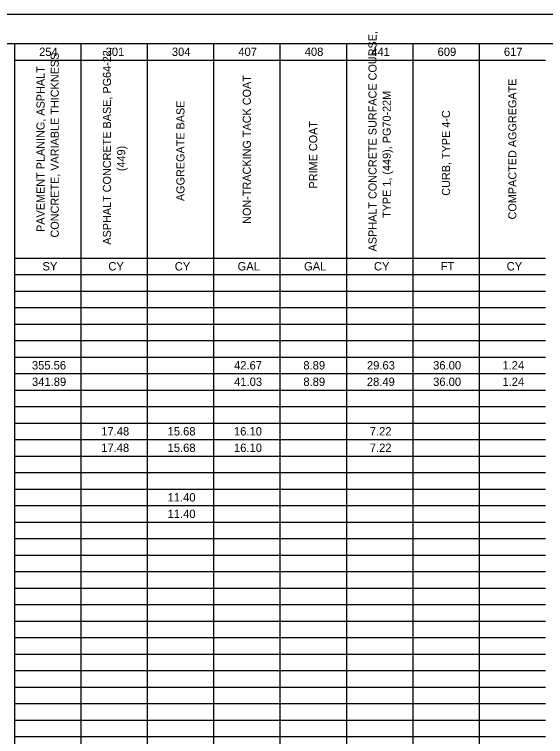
# Model space of a CAD drawing. Extents: x 0 to 34, y 0 to 22.
# Drawn here: x 16.02 to 25.15, y 9.58 to 22 of the extents above; entities that cross this region are included whole.
import ezdxf

# ---------------------------------------------------------------- set-up
doc = ezdxf.new("R2010")
doc.units = 0
for name, color, linetype in [('SH_Border', 7, 'Continuous'), ('SH_Cut_Line', 7, 'Continuous'), ('SH_Text', 7, 'Continuous')]:
    doc.layers.add(name, color=color, linetype=linetype)

msp = doc.modelspace()

# ---------------------------------------------------------------- linework, layer by layer
at = {"layer": 'SH_Border'}
msp.add_lwpolyline([(1.5, 21.5), (33.5, 21.5), (33.5, 0.5), (1.5, 0.5)], close=True, dxfattribs=at)
at = {"layer": 'SH_Cut_Line'}
msp.add_lwpolyline([(0, 0), (34, 0), (34, 22), (0, 22)], close=True, dxfattribs=at)
at = {"layer": 'SH_Text'}
for p, q in [((16.022, 21.5), (24.011, 21.5)), ((16.022, 21.5), (16.022, 21.216)), ((17.163, 21.5), (17.163, 21.216)), ((18.305, 21.5), (18.305, 21.216)), ((19.446, 21.5), (19.446, 21.216)), ((20.587, 21.5), (20.587, 21.216)), ((21.728, 21.5), (21.728, 21.216)), ((22.87, 21.5), (22.87, 21.216)), ((24.011, 21.5), (25.152, 21.5)), ((24.011, 21.5), (24.011, 21.216)), ((16.022, 21.216), (24.011, 21.216)), ((16.022, 21.216), (16.022, 20.932)), ((17.163, 21.216), (17.163, 20.932)), ((18.305, 21.216), (18.305, 20.932)), ((19.446, 21.216), (19.446, 20.932)), ((20.587, 21.216), (20.587, 20.932)), ((21.728, 21.216), (21.728, 20.932)), ((22.87, 21.216), (22.87, 20.932)), ((24.011, 21.216), (25.152, 21.216)), ((24.011, 21.216), (24.011, 20.932)), ((16.022, 20.932), (16.022, 20.649)), ((17.163, 20.932), (17.163, 20.649)), ((18.305, 20.932), (18.305, 20.649)), ((19.446, 20.932), (19.446, 20.649)), ((20.587, 20.932), (20.587, 20.649)), ((21.728, 20.932), (21.728, 20.649)), ((22.87, 20.932), (22.87, 20.649)), ((24.011, 20.932), (24.011, 20.649)), ((16.022, 20.649), (16.022, 20.081)), ((17.163, 20.649), (17.163, 20.081)), ((18.305, 20.649), (18.305, 20.081)), ((19.446, 20.649), (19.446, 20.081)), ((20.587, 20.649), (20.587, 20.081)), ((21.728, 20.649), (21.728, 20.081)), ((22.87, 20.649), (22.87, 20.081)), ((24.011, 20.649), (24.011, 20.081)), ((16.022, 20.081), (16.022, 19.797)), ((17.163, 20.081), (17.163, 19.797)), ((18.305, 20.081), (18.305, 19.797)), ((19.446, 20.081), (19.446, 19.797)), ((20.587, 20.081), (20.587, 19.797)), ((21.728, 20.081), (21.728, 19.797)), ((22.87, 20.081), (22.87, 19.797)), ((24.011, 20.081), (24.011, 19.797)), ((16.022, 19.797), (16.022, 19.514)), ((17.163, 19.797), (17.163, 19.514)), ((18.305, 19.797), (18.305, 19.514)), ((19.446, 19.797), (19.446, 19.514)), ((20.587, 19.797), (20.587, 19.514)), ((21.728, 19.797), (21.728, 19.514)), ((22.87, 19.797), (22.87, 19.514)), ((24.011, 19.797), (24.011, 19.514)), ((16.022, 19.514), (16.022, 19.23)), ((17.163, 19.514), (17.163, 19.23)), ((18.305, 19.514), (18.305, 19.23)), ((19.446, 19.514), (19.446, 19.23)), ((20.587, 19.514), (20.587, 19.23)), ((21.728, 19.514), (21.728, 19.23)), ((22.87, 19.514), (22.87, 19.23)), ((24.011, 19.514), (24.011, 19.23)), ((16.022, 19.23), (16.022, 18.946)), ((17.163, 19.23), (17.163, 18.946)), ((18.305, 19.23), (18.305, 18.946)), ((19.446, 19.23), (19.446, 18.946)), ((20.587, 19.23), (20.587, 18.946)), ((21.728, 19.23), (21.728, 18.946)), ((22.87, 19.23), (22.87, 18.946)), ((24.011, 19.23), (24.011, 18.946)), ((16.022, 18.946), (16.022, 18.662)), ((17.163, 18.946), (17.163, 18.662)), ((18.305, 18.946), (18.305, 18.662)), ((19.446, 18.946), (19.446, 18.662)), ((20.587, 18.946), (20.587, 18.662)), ((21.728, 18.946), (21.728, 18.662)), ((22.87, 18.946), (22.87, 18.662)), ((24.011, 18.946), (24.011, 18.662)), ((16.022, 18.662), (16.022, 18.378)), ((17.163, 18.662), (17.163, 18.378)), ((18.305, 18.662), (18.305, 18.378)), ((19.446, 18.662), (19.446, 18.378)), ((20.587, 18.662), (20.587, 18.378)), ((21.728, 18.662), (21.728, 18.378)), ((22.87, 18.662), (22.87, 18.378)), ((24.011, 18.662), (24.011, 18.378)), ((16.022, 18.378), (16.022, 18.095)), ((17.163, 18.378), (17.163, 18.095)), ((18.305, 18.378), (18.305, 18.095)), ((19.446, 18.378), (19.446, 18.095)), ((20.587, 18.378), (20.587, 18.095)), ((21.728, 18.378), (21.728, 18.095)), ((22.87, 18.378), (22.87, 18.095)), ((24.011, 18.378), (24.011, 18.095)), ((16.022, 18.095), (16.022, 17.811)), ((17.163, 18.095), (17.163, 17.811)), ((18.305, 18.095), (18.305, 17.811)), ((19.446, 18.095), (19.446, 17.811)), ((20.587, 18.095), (20.587, 17.811)), ((21.728, 18.095), (21.728, 17.811)), ((22.87, 18.095), (22.87, 17.811)), ((24.011, 18.095), (24.011, 17.811)), ((16.022, 17.811), (24.011, 17.811)), ((16.022, 17.811), (16.022, 17.527)), ((17.163, 17.811), (17.163, 17.527)), ((18.305, 17.811), (18.305, 17.527)), ((19.446, 17.811), (19.446, 17.527)), ((20.587, 17.811), (20.587, 17.527)), ((21.728, 17.811), (21.728, 17.527)), ((22.87, 17.811), (22.87, 17.527)), ((24.011, 17.811), (25.152, 17.811)), ((24.011, 17.811), (24.011, 17.527)), ((16.022, 17.527), (24.011, 17.527)), ((16.022, 17.527), (16.022, 17.243)), ((17.163, 17.527), (17.163, 17.243)), ((18.305, 17.527), (18.305, 17.243)), ((19.446, 17.527), (19.446, 17.243)), ((20.587, 17.527), (20.587, 17.243)), ((21.728, 17.527), (21.728, 17.243)), ((22.87, 17.527), (22.87, 17.243)), ((24.011, 17.527), (25.152, 17.527)), ((24.011, 17.527), (24.011, 17.243)), ((16.022, 17.243), (24.011, 17.243)), ((16.022, 17.243), (16.022, 16.959)), ((17.163, 17.243), (17.163, 16.959)), ((18.305, 17.243), (18.305, 16.959)), ((19.446, 17.243), (19.446, 16.959)), ((20.587, 17.243), (20.587, 16.959)), ((21.728, 17.243), (21.728, 16.959)), ((22.87, 17.243), (22.87, 16.959)), ((24.011, 17.243), (25.152, 17.243)), ((24.011, 17.243), (24.011, 16.959)), ((16.022, 16.959), (24.011, 16.959)), ((16.022, 16.959), (16.022, 16.676)), ((17.163, 16.959), (17.163, 16.676)), ((18.305, 16.959), (18.305, 16.676)), ((19.446, 16.959), (19.446, 16.676)), ((20.587, 16.959), (20.587, 16.676)), ((21.728, 16.959), (21.728, 16.676)), ((22.87, 16.959), (22.87, 16.676)), ((24.011, 16.959), (25.152, 16.959)), ((24.011, 16.959), (24.011, 16.676)), ((16.022, 16.676), (24.011, 16.676)), ((16.022, 16.676), (16.022, 16.108)), ((17.163, 16.676), (17.163, 16.108)), ((18.305, 16.676), (18.305, 16.108)), ((19.446, 16.676), (19.446, 16.108)), ((20.587, 16.676), (20.587, 16.108)), ((21.728, 16.676), (21.728, 16.108)), ((22.87, 16.676), (22.87, 16.108)), ((24.011, 16.676), (25.152, 16.676)), ((24.011, 16.676), (24.011, 16.108)), ((16.022, 16.392), (24.011, 16.392)), ((24.011, 16.392), (25.152, 16.392)), ((16.022, 16.108), (24.011, 16.108)), ((16.022, 16.108), (16.022, 15.824)), ((17.163, 16.108), (17.163, 15.824)), ((18.305, 16.108), (18.305, 15.824)), ((19.446, 16.108), (19.446, 15.824)), ((20.587, 16.108), (20.587, 15.824)), ((21.728, 16.108), (21.728, 15.824)), ((22.87, 16.108), (22.87, 15.824)), ((24.011, 16.108), (25.152, 16.108)), ((24.011, 16.108), (24.011, 15.824)), ((16.022, 15.824), (24.011, 15.824)), ((16.022, 15.824), (16.022, 15.541)), ((17.163, 15.824), (17.163, 15.541)), ((18.305, 15.824), (18.305, 15.541)), ((19.446, 15.824), (19.446, 15.541)), ((20.587, 15.824), (20.587, 15.541)), ((21.728, 15.824), (21.728, 15.541)), ((22.87, 15.824), (22.87, 15.541)), ((24.011, 15.824), (25.152, 15.824)), ((24.011, 15.824), (24.011, 15.541)), ((16.022, 15.541), (24.011, 15.541)), ((16.022, 15.541), (16.022, 15.257)), ((17.163, 15.541), (17.163, 15.257)), ((18.305, 15.541), (18.305, 15.257)), ((19.446, 15.541), (19.446, 15.257)), ((20.587, 15.541), (20.587, 15.257)), ((21.728, 15.541), (21.728, 15.257)), ((22.87, 15.541), (22.87, 15.257)), ((24.011, 15.541), (25.152, 15.541)), ((24.011, 15.541), (24.011, 15.257)), ((16.022, 15.257), (24.011, 15.257)), ((16.022, 15.257), (16.022, 14.689)), ((17.163, 15.257), (17.163, 14.689)), ((18.305, 15.257), (18.305, 14.689)), ((19.446, 15.257), (19.446, 14.689)), ((20.587, 15.257), (20.587, 14.689)), ((21.728, 15.257), (21.728, 14.689)), ((22.87, 15.257), (22.87, 14.689)), ((24.011, 15.257), (25.152, 15.257)), ((24.011, 15.257), (24.011, 14.689)), ((16.022, 14.973), (24.011, 14.973)), ((24.011, 14.973), (25.152, 14.973)), ((16.022, 14.689), (24.011, 14.689)), ((16.022, 14.689), (16.022, 14.405)), ((17.163, 14.689), (17.163, 14.405)), ((18.305, 14.689), (18.305, 14.405)), ((19.446, 14.689), (19.446, 14.405)), ((20.587, 14.689), (20.587, 14.405)), ((21.728, 14.689), (21.728, 14.405)), ((22.87, 14.689), (22.87, 14.405)), ((24.011, 14.689), (25.152, 14.689)), ((24.011, 14.689), (24.011, 14.405)), ((16.022, 14.405), (24.011, 14.405)), ((16.022, 14.405), (16.022, 14.122)), ((17.163, 14.405), (17.163, 14.122)), ((18.305, 14.405), (18.305, 14.122)), ((19.446, 14.405), (19.446, 14.122)), ((20.587, 14.405), (20.587, 14.122)), ((21.728, 14.405), (21.728, 14.122)), ((22.87, 14.405), (22.87, 14.122)), ((24.011, 14.405), (25.152, 14.405)), ((24.011, 14.405), (24.011, 14.122)), ((16.022, 14.122), (24.011, 14.122)), ((16.022, 14.122), (16.022, 13.838)), ((17.163, 14.122), (17.163, 13.838)), ((18.305, 14.122), (18.305, 13.838)), ((19.446, 14.122), (19.446, 13.838)), ((20.587, 14.122), (20.587, 13.838)), ((21.728, 14.122), (21.728, 13.838)), ((22.87, 14.122), (22.87, 13.838)), ((24.011, 14.122), (25.152, 14.122)), ((24.011, 14.122), (24.011, 13.838)), ((16.022, 13.838), (24.011, 13.838)), ((16.022, 13.838), (16.022, 12.986)), ((17.163, 13.838), (17.163, 12.986)), ((18.305, 13.838), (18.305, 12.986)), ((19.446, 13.838), (19.446, 12.986)), ((20.587, 13.838), (20.587, 12.986)), ((21.728, 13.838), (21.728, 12.986)), ((22.87, 13.838), (22.87, 12.986)), ((24.011, 13.838), (25.152, 13.838)), ((24.011, 13.838), (24.011, 12.986)), ((16.022, 13.554), (24.011, 13.554)), ((24.011, 13.554), (25.152, 13.554)), ((16.022, 13.27), (24.011, 13.27)), ((24.011, 13.27), (25.152, 13.27)), ((16.022, 12.986), (24.011, 12.986)), ((16.022, 12.986), (16.022, 12.703)), ((17.163, 12.986), (17.163, 12.703)), ((18.305, 12.986), (18.305, 12.703)), ((19.446, 12.986), (19.446, 12.703)), ((20.587, 12.986), (20.587, 12.703)), ((21.728, 12.986), (21.728, 12.703)), ((22.87, 12.986), (22.87, 12.703)), ((24.011, 12.986), (25.152, 12.986)), ((24.011, 12.986), (24.011, 12.703)), ((16.022, 12.703), (24.011, 12.703)), ((16.022, 12.703), (16.022, 11.568)), ((17.163, 12.703), (17.163, 11.568)), ((18.305, 12.703), (18.305, 11.568)), ((19.446, 12.703), (19.446, 11.568)), ((20.587, 12.703), (20.587, 11.568)), ((21.728, 12.703), (21.728, 11.568)), ((22.87, 12.703), (22.87, 11.568)), ((24.011, 12.703), (25.152, 12.703)), ((24.011, 12.703), (24.011, 11.568)), ((16.022, 12.419), (24.011, 12.419)), ((24.011, 12.419), (25.152, 12.419)), ((16.022, 12.135), (24.011, 12.135)), ((24.011, 12.135), (25.152, 12.135)), ((16.022, 11.851), (24.011, 11.851)), ((24.011, 11.851), (25.152, 11.851)), ((16.022, 11.568), (24.011, 11.568)), ((16.022, 11.568), (16.022, 11.284)), ((17.163, 11.568), (17.163, 11.284)), ((18.305, 11.568), (18.305, 11.284)), ((19.446, 11.568), (19.446, 11.284)), ((20.587, 11.568), (20.587, 11.284)), ((21.728, 11.568), (21.728, 11.284)), ((22.87, 11.568), (22.87, 11.284)), ((24.011, 11.568), (25.152, 11.568)), ((24.011, 11.568), (24.011, 11.284)), ((16.022, 11.284), (24.011, 11.284)), ((16.022, 11.284), (16.022, 10.149)), ((17.163, 11.284), (17.163, 10.149)), ((18.305, 11.284), (18.305, 10.149)), ((19.446, 11.284), (19.446, 10.149)), ((20.587, 11.284), (20.587, 10.149)), ((21.728, 11.284), (21.728, 10.149)), ((22.87, 11.284), (22.87, 10.149)), ((24.011, 11.284), (25.152, 11.284)), ((24.011, 11.284), (24.011, 10.149)), ((16.022, 11), (24.011, 11)), ((24.011, 11), (25.152, 11)), ((16.022, 10.716), (24.011, 10.716)), ((24.011, 10.716), (25.152, 10.716)), ((16.022, 10.432), (24.011, 10.432)), ((24.011, 10.432), (25.152, 10.432)), ((16.022, 10.149), (24.011, 10.149)), ((16.022, 10.149), (16.022, 9.581)), ((17.163, 10.149), (17.163, 9.581)), ((18.305, 10.149), (18.305, 9.581)), ((19.446, 10.149), (19.446, 9.581)), ((20.587, 10.149), (20.587, 9.581)), ((21.728, 10.149), (21.728, 9.581)), ((22.87, 10.149), (22.87, 9.581)), ((24.011, 10.149), (25.152, 10.149)), ((24.011, 10.149), (24.011, 9.581)), ((16.022, 9.865), (24.011, 9.865)), ((24.011, 9.865), (25.152, 9.865)), ((16.022, 9.581), (24.011, 9.581)), ((16.022, 9.581), (16.022, 9.297)), ((17.163, 9.581), (17.163, 9.297)), ((18.305, 9.581), (18.305, 9.297)), ((19.446, 9.581), (19.446, 9.297)), ((20.587, 9.581), (20.587, 9.297)), ((21.728, 9.581), (21.728, 9.297)), ((22.87, 9.581), (22.87, 9.297)), ((24.011, 9.581), (25.152, 9.581)), ((24.011, 9.581), (24.011, 9.297))]:
    msp.add_line(p, q, dxfattribs=at)

# ---------------------------------------------------------------- texts
for s, height, p in [('ASPHALT CONCRETE SURFACE COURSE, ', 0.13938, (22.247, 17.924)), ('ASPHALT CONCRETE BASE, PG64-22, ', 0.13938, (17.682, 18.04)), ('CONCRETE, VARIABLE THICKNESS', 0.13938, (16.784, 18.163)), ('PAVEMENT PLANING, ASPHALT ', 0.13938, (16.54, 18.26)), ('NON-TRACKING TACK COAT', 0.13938, (20.086, 18.399)), ('COMPACTED AGGREGATE', 0.13938, (24.651, 18.474)), ('TYPE 1, (449), PG70-22M', 0.13938, (22.491, 18.5)), ('AGGREGATE BASE', 0.13938, (18.945, 18.79)), ('CURB, TYPE 4-C', 0.13938, (23.51, 18.882)), ('PRIME COAT', 0.1394, (21.227, 19.007)), ('(449)', 0.1394, (17.926, 19.305))]:
    msp.add_text(s, height=height, rotation=90, dxfattribs=at).set_placement(p)
for s, p in [('254', (16.446, 21.286)), ('301', (17.589, 21.286)), ('304', (18.728, 21.286)), ('407', (19.871, 21.286)), ('408', (21.012, 21.286)), ('441', (22.155, 21.286)), ('609', (23.296, 21.286)), ('617', (24.436, 21.286)), ('SY', (16.504, 17.597)), ('CY', (17.636, 17.597)), ('CY', (18.778, 17.597)), ('GAL', (19.858, 17.597)), ('GAL', (21, 17.597)), ('CY', (22.202, 17.597)), ('FT', (23.348, 17.597)), ('CY', (24.484, 17.597)), ('355.56', (16.322, 15.894)), ('42.67', (19.797, 15.894)), ('8.89', (20.989, 15.894)), ('29.63', (22.082, 15.894)), ('36.00', (23.22, 15.894)), ('1.24', (24.411, 15.894)), ('341.89', (16.324, 15.611)), ('41.03', (19.799, 15.611)), ('8.89', (20.989, 15.611)), ('28.49', (22.08, 15.611)), ('36.00', (23.22, 15.611)), ('1.24', (24.411, 15.611)), ('17.48', (17.514, 14.759)), ('15.68', (18.655, 14.759)), ('16.10', (19.796, 14.759)), ('7.22', (22.131, 14.759)), ('17.48', (17.514, 14.476)), ('15.68', (18.655, 14.476)), ('16.10', (19.796, 14.476)), ('7.22', (22.131, 14.476)), ('11.40', (18.655, 13.624)), ('11.40', (18.655, 13.34))]:
    msp.add_text(s, height=0.1436, dxfattribs=at).set_placement(p)

doc.saveas('drawing.dxf')
